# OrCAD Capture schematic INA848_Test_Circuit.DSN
size A; title: INA848 Ultra-Low-Noise (1.5 nV/vHz), High-Bandwidth; rev: 1.1; note: Datasheet: SBOS946   EVM: NA
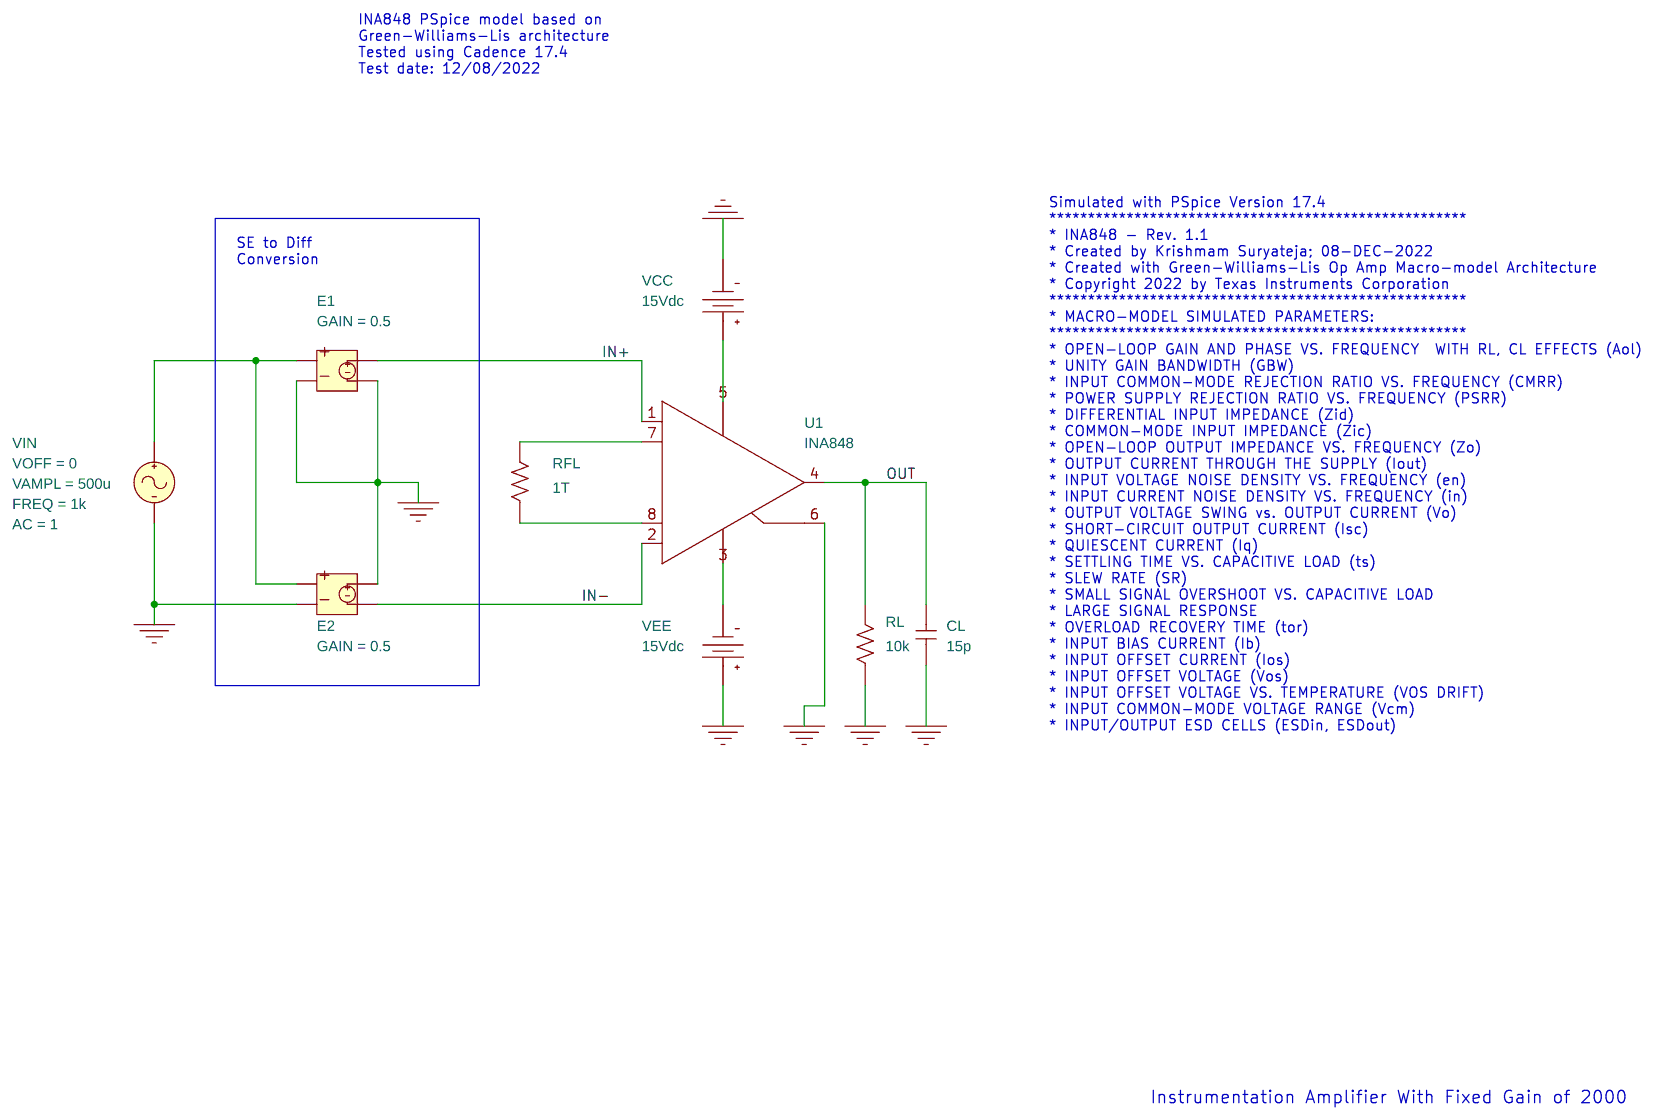
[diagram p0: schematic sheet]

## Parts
CL  15p  [RAD/CK05]
E1  E
E2  E
RFL  1T  [AXRC05]
RL  10k  [AXRC05]
U1  INA848
VCC  VDC
VEE  VDC
VIN  VSIN

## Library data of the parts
CL = C
E1 E2 = E: GAIN: 0.5
RFL RL = R
U1 = INA848
VCC VEE = VDC: DC: 15Vdc
VIN = VSIN: AC: 1; FREQ: 1k; VAMPL: 500u; VOFF: 0

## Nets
0: CL.1 E1.2 E1.4 E2.2 E2.3 RL.1 U1.6(REF) VCC.1(-) VEE.0(+) VIN.2(-)
IN+: E1.3 U1.1(+)
IN-: E2.4 U1.2(-)
OUT: CL.2 RL.2 U1.4(OUT)
N28695: E1.1 E2.1 VIN.1(+)
N28767: RFL.2 U1.7(+FL)
N28823: RFL.1 U1.8(-FL)
N29049: U1.5(V+) VCC.0(+)
N31704: U1.3(V-) VEE.1(-)

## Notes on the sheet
- INA848 PSpice model based on
  Green-Williams-Lis architecture
  Tested using Cadence 17.4
  Test date: 12/08/2022
- Simulated with PSpice Version 17.4
  ******************************************************
  * INA848 - Rev. 1.1
  * Created by Krishmam Suryateja; 08-DEC-2022
  * Created with Green-Williams-Lis Op Amp Macro-model Architecture
  * Copyright 2022 by Texas Instruments Corporation
  ******************************************************
  * MACRO-MODEL SIMULATED PARAMETERS:
  ******************************************************
  * OPEN-LOOP GAIN AND PHASE VS. FREQUENCY  WITH RL, CL EFFECTS (Aol)
  * UNITY GAIN BANDWIDTH (GBW)
  * INPUT COMMON-MODE REJECTION RATIO VS. FREQUENCY (CMRR)
  * POWER SUPPLY REJECTION RATIO VS. FREQUENCY (PSRR)
  * DIFFERENTIAL INPUT IMPEDANCE (Zid)
  * COMMON-MODE INPUT IMPEDANCE (Zic)
  * OPEN-LOOP OUTPUT IMPEDANCE VS. FREQUENCY (Zo)
  * OUTPUT CURRENT THROUGH THE SUPPLY (Iout)
  * INPUT VOLTAGE NOISE DENSITY VS. FREQUENCY (en)
  * INPUT CURRENT NOISE DENSITY VS. FREQUENCY (in)
  * OUTPUT VOLTAGE SWING vs. OUTPUT CURRENT (Vo)
  * SHORT-CIRCUIT OUTPUT CURRENT (Isc)
  * QUIESCENT CURRENT (Iq)
  * SETTLING TIME VS. CAPACITIVE LOAD (ts)
  * SLEW RATE (SR)
  * SMALL SIGNAL OVERSHOOT VS. CAPACITIVE LOAD
  * LARGE SIGNAL RESPONSE
  * OVERLOAD RECOVERY TIME (tor)
  * INPUT BIAS CURRENT (Ib)
  * INPUT OFFSET CURRENT (Ios)
  * INPUT OFFSET VOLTAGE (Vos)
  * INPUT OFFSET VOLTAGE VS. TEMPERATURE (VOS DRIFT)
  * INPUT COMMON-MODE VOLTAGE RANGE (Vcm)
  * INPUT/OUTPUT ESD CELLS (ESDin, ESDout)
- SE to Diff
  Conversion
- Instrumentation Amplifier With Fixed Gain of 2000
